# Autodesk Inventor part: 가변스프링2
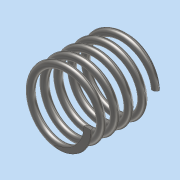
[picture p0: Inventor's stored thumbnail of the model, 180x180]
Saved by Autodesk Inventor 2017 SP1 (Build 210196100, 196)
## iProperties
Part Number: 가변스프링2
Material: 스테인레스 스틸
Document SubType Name: Modeling
Designer: MRC
Density: 8 g/cm^3
Appearance: 반연마
Mass: 6.96277 g
Surface Area: 17.6923 cm^2
Volume: 0.870346 cm^3
Author: MRC
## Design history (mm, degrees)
sketch "스케치1"
  geometry: L1 (0, 0)-(0, 19.5); L2 (0, 19.5)-(9, 19.5); L3 (0, 0)-(9, 0); C1 r 1 at (9, 0)
  constraints: 6 end point, 1 centre point, 1 coincident, 1 horizontal, 1 perpendicular, 1 vertical
  dimensions: "d0" = 19.5 distance of L1.start L1.end (derived); "d1" = 9 distance of L1.end L2.end; "d2" = 9 distance of L1.start L3.end; "d3" = 2 diameter of C1
feature "코일1" pitch "d4" = 10; turns "d6" = 5; dims "d5" = 19.5 (= d0), "d7" = 0, angle "d8" = 90 deg, angle "d9" = 90 deg, "d10" = 0, "d11" = 0
sketch "스케치2"
  geometry: L1 (19.5, 15)-(0, 15); L2 (0, 15)-(0, -15); L3 (0, -15)-(19.5, -15); L4 (19.5, -15)-(19.5, 15); 2 further points
  constraints: 8 end point, 2 midpoint, 2 parallel, 1 coincident, 1 horizontal, 1 perpendicular
  dimensions: "d12" = 30 distance of L3.end L1.start; "d13" = 19.5 distance of L1.start L1.end (= d0)
extrude "돌출2" sketch "스케치2" stored distance "d16" = 0; taper "d17" = 0 deg
node "솔리드1"
